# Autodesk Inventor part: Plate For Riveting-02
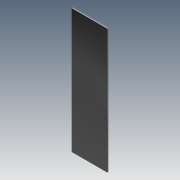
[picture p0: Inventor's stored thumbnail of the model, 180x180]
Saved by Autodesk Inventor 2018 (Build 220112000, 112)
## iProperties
Created: 2018-02
Part Number: Plate For Riveting-02
Material: Steel, Mild
Document SubType Name: Modeling
Designer: STK
Density: 7.85 g/cm^3
Appearance: Semi-Polished
Author: STK
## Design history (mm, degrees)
derived "Plate For Riveting.ipt"
feature "Solid1::Plate For Riveting.ipt"
tag "TaggingFeature1"
body "Solid1"
other parameters: "Width" = 304.8, "Length" = 1066.8, "Thickness" = 9.525, "d3" = 0
